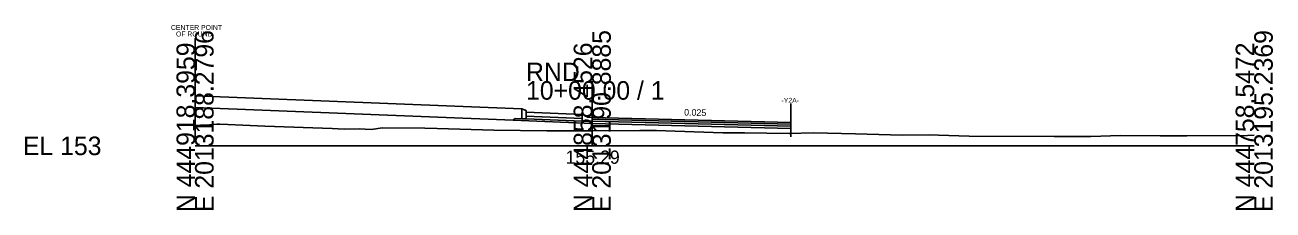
# Model space of a CAD drawing. Extents: x -26 to 163, y -10 to 7518.
# Drawn here: x -25.7 to 162.8, y -9.7 to 18.3 of the extents above; entities that cross this region are included whole.
import ezdxf

# ---------------------------------------------------------------- set-up
doc = ezdxf.new("R2010")
doc.units = 0
for name, color, linetype in [('Exist Cross Section Cell', 7, 'Continuous'), ('Exist XS Center Line Elevation Label', 7, 'Continuous'), ('Exist XS Ground Line', 7, 'Continuous'), ('Prop CMT Conc Surface', 7, 'Continuous'), ('Prop CMT Concrete Structures', 7, 'Continuous'), ('Prop CMT Pvmt Course 1', 7, 'Continuous'), ('Prop CMT Pvmt Course 1 CG', 7, 'Continuous'), ('Prop CMT Pvmt Course 2', 7, 'Continuous'), ('Prop CMT Pvmt Course 3', 7, 'Continuous'), ('Prop CMT Pvmt Surface', 7, 'Continuous'), ('Prop CMT Shear Line', 7, 'Continuous'), ('Prop CMT Shear Line Text', 7, 'Continuous'), ('Prop CMT Slope Grass', 7, 'Continuous'), ('Prop CMT Subgrade Earthwork', 7, 'Continuous'), ('Prop XS Earthwork Shape', 7, 'Continuous'), ('Prop XS SE Text', 7, 'Continuous')]:
    doc.layers.add(name, color=color, linetype=linetype)

msp = doc.modelspace()

# ---------------------------------------------------------------- linework, layer by layer
at = {"layer": 'Exist Cross Section Cell'}
for p, q in [((60, 0), (60, 9.77)), ((0, 0), (60, 0)), ((60, 0), (160, 0))]:
    msp.add_line(p, q, dxfattribs=at)
at = {"layer": 'Exist XS Ground Line'}
msp.add_lwpolyline([(0, 3.05), (0.81, 3.1), (2.16, 3.19), (3.31, 3.26), (3.72, 3.26), (4.96, 3.24), (7.23, 3.13), (10.54, 2.96), (20.69, 2.61), (22.53, 2.54), (24.77, 2.59), (26.59, 2.49), (28.31, 2.7), (34.73, 2.66), (36.58, 2.61), (45.11, 2.38), (53.12, 2.28), (58.82, 2.29), (60, 2.29), (67.18, 2.3), (69.73, 2.3), (72.51, 2.22), (79.74, 1.98), (82.98, 1.96), (89.75, 1.86), (93.44, 1.96), (99.76, 1.79), (106.83, 1.62), (110.92, 1.66), (112.32, 1.63), (116.96, 1.46), (129.79, 1.43), (135.31, 1.43), (139.8, 1.54), (145.78, 1.49), (149.81, 1.51), (158.99, 1.58), (160, 1.59)], dxfattribs=at)
at = {"layer": 'Prop CMT Conc Surface'}
for points in [[(50, 5.26), (49.96, 5.37), (49.85, 5.41), (49.34, 5.6)], [(50, 5.1), (50, 5.26)], [(60, 4.3), (59.25, 4.32), (59.25, 4.49), (58.5, 4.74)]]:
    msp.add_lwpolyline(points, dxfattribs=at)
at = {"layer": 'Prop CMT Concrete Structures'}
for points in [[(50, 5.26), (49.96, 5.37), (49.85, 5.41), (49.34, 5.6)], [(49.34, 5.6), (49.34, 4.1)], [(49.34, 4.1), (50, 4.1)], [(50, 5.1), (50, 5.26)], [(50, 4.1), (50, 5.1)], [(50, 5.1), (50, 4.51)], [(58.5, 4.74), (50, 5.08)], [(50, 4.49), (58.5, 4.15)], [(60, 4.3), (59.25, 4.32), (59.25, 4.49), (58.5, 4.74)], [(58.5, 4.74), (58.5, 3.75)], [(58.5, 4.15), (58.5, 4.74)], [(60, 3.72), (60, 4.3)], [(58.5, 3.75), (60, 3.72)]]:
    msp.add_lwpolyline(points, dxfattribs=at)
at = {"layer": 'Prop CMT Pvmt Course 1'}
for points in [[(60, 4.3), (90, 3.55)], [(60, 4.05), (60, 4.3)], [(90, 3.3), (60, 4.05)], [(90, 3.55), (90, 3.3)]]:
    msp.add_lwpolyline(points, dxfattribs=at)
msp.add_lwpolyline([(60, 4.05), (60, 4.17), (60, 4.17), (60, 4.05)], close=True, dxfattribs=at)
at = {"layer": 'Prop CMT Pvmt Course 1 CG'}
for points in [[(60, 3.38), (60, 3.72)], [(90, 2.63), (90, 2.96)]]:
    msp.add_lwpolyline(points, dxfattribs=at)
at = {"layer": 'Prop CMT Pvmt Course 2'}
for points in [[(60, 3.72), (60, 4.05)], [(60, 4.05), (90, 3.3)], [(90, 2.96), (60, 3.72)], [(90, 3.3), (90, 2.96)]]:
    msp.add_lwpolyline(points, dxfattribs=at)
at = {"layer": 'Prop CMT Pvmt Course 3'}
for points in [[(50, 4.1), (58.5, 3.75)], [(60, 3.72), (90, 2.96)], [(60, 3.38), (60, 3.72)], [(90, 2.63), (60, 3.38)], [(90, 2.96), (90, 2.63)]]:
    msp.add_lwpolyline(points, dxfattribs=at)
at = {"layer": 'Prop CMT Pvmt Surface'}
msp.add_lwpolyline([(60, 4.3), (90, 3.55)], dxfattribs=at)
at = {"layer": 'Prop CMT Shear Line'}
for p, q in [((0, 1.24), (0, 16.24)), ((90, 1.37), (90, 6.39))]:
    msp.add_line(p, q, dxfattribs=at)
at = {"layer": 'Prop CMT Slope Grass'}
for p, q in [((49.34, 5.58), (0, 7.55)), ((48.06, 3.86), (0, 5.78))]:
    msp.add_line(p, q, dxfattribs=at)
at = {"layer": 'Prop CMT Subgrade Earthwork'}
for p, q in [((0, 7.55), (0, 3.05)), ((48.34, 4.14), (48.06, 3.86)), ((90, 3.55), (90, 1.86))]:
    msp.add_line(p, q, dxfattribs=at)
for points in [[(48.06, 3.86), (60, 3.38)], [(48.34, 4.14), (49.34, 4.1)], [(60, 3.38), (90, 2.63)]]:
    msp.add_lwpolyline(points, dxfattribs=at)
at = {"layer": 'Prop XS Earthwork Shape'}
msp.add_lwpolyline([(58.82, 2.29), (60, 2.29), (67.18, 2.3), (69.73, 2.3), (72.51, 2.22), (79.74, 1.98), (82.98, 1.96), (89.75, 1.86), (90, 1.86), (90, 2.63), (60, 3.38), (48.06, 3.86), (0, 5.78), (0, 3.05), (0.81, 3.1), (2.16, 3.19), (3.31, 3.26), (3.72, 3.26), (4.96, 3.24), (7.23, 3.13), (10.54, 2.96), (20.69, 2.61), (22.53, 2.54), (24.77, 2.59), (26.59, 2.49), (28.31, 2.7), (34.73, 2.66), (36.58, 2.61), (45.11, 2.38), (53.12, 2.28)], close=True, dxfattribs=at)

# ---------------------------------------------------------------- texts
at = {"layer": 'Exist Cross Section Cell'}
for s, p in [('E 2013188.2796', (2.8, -10)), ('E 2013190.8885', (62.8, -10)), ('E 2013195.2369', (162.8, -10)), ('N 444918.3959', (0, -10)), ('N 444858.4526', (60, -10)), ('N 444758.5472', (160, -10))]:
    msp.add_text(s, height=2.8, rotation=90, dxfattribs=at).set_placement(p)
for s, p in [('RND', (50, 9.77)), ('10+00.00 / 1', (50, 6.97)), ('EL 153', (-26, -1.4))]:
    msp.add_text(s, height=2.8, dxfattribs=at).set_placement(p)
at = {"layer": 'Exist XS Center Line Elevation Label'}
msp.add_text('155.29', height=2, dxfattribs=at).set_placement((55.97, -2.71))
at = {"layer": 'Prop CMT Shear Line Text'}
for s, p in [('CENTER POINT', (-3.64, 17.5)), ('OF ROUND', (-2.88, 16.52)), ('-Y2A-', (88.59, 6.5))]:
    msp.add_text(s, height=0.75, dxfattribs=at).set_placement(p)
at = {"layer": 'Prop XS SE Text'}
msp.add_text('0.025', height=1, rotation=358.5613, dxfattribs=at).set_placement((73.87, 4.58))

doc.saveas('drawing.dxf')
